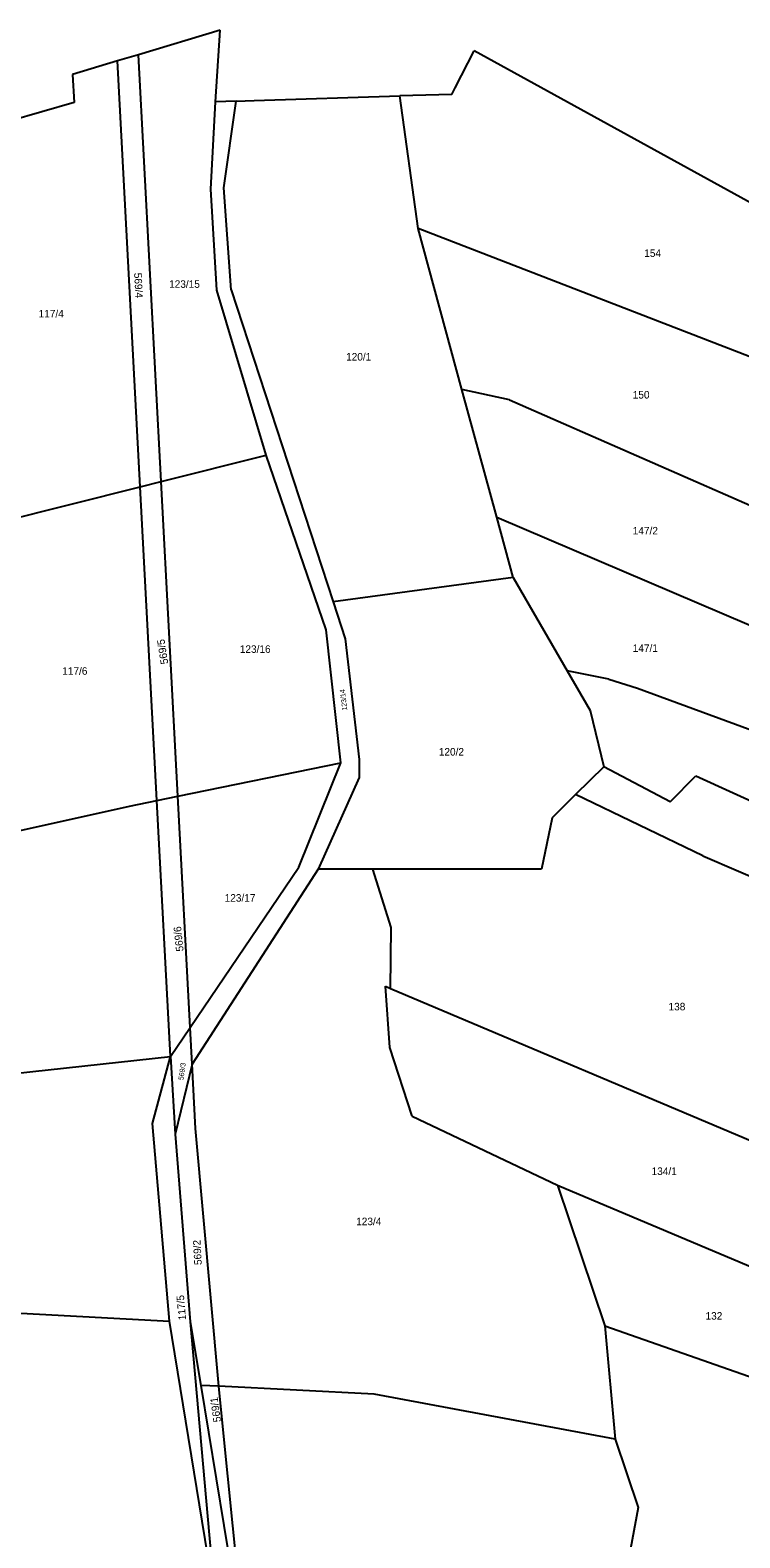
# Model space of a CAD drawing. Extents: x -664548 to -662415, y -1069720 to -1068208.
# Drawn here: x -663711.8 to -663551.7, y -1068707.2 to -1068366.8 of the extents above; entities that cross this region are included whole.
import ezdxf

# ---------------------------------------------------------------- set-up
doc = ezdxf.new("R2010")
doc.units = 0
doc.header["$LTSCALE"] = 0.68
doc.layers.add('1', color=7, linetype='Continuous', lineweight=25)
doc.layers.add('2', color=7, linetype='Continuous')

msp = doc.modelspace()

# ---------------------------------------------------------------- linework, layer by layer
at = {"layer": '1'}
for p, q in [((-663668.96, -1068366.83), (-663687.39, -1068372.38)), ((-663670.03, -1068382.99), (-663668.96, -1068366.83)), ((-663687.39, -1068372.38), (-663692.09, -1068373.79)), ((-663682.27, -1068468.73), (-663687.39, -1068372.38)), ((-663615.91, -1068379.83), (-663611.63, -1068371.51)), ((-663510.93, -1068426.96), (-663611.63, -1068371.51)), ((-663692.09, -1068373.79), (-663702.26, -1068376.85)), ((-663686.99, -1068469.92), (-663692.09, -1068373.79)), ((-663702.26, -1068376.85), (-663701.89, -1068383.2)), ((-663616.68, -1068381.33), (-663615.91, -1068379.83)), ((-663671.04, -1068402.75), (-663670.03, -1068382.99)), ((-663665.32, -1068382.84), (-663670.03, -1068382.99)), ((-663668.15, -1068402.4), (-663665.32, -1068382.84)), ((-663665.32, -1068382.84), (-663661.3, -1068382.71)), ((-663661.3, -1068382.71), (-663628.4, -1068381.69)), ((-663616.68, -1068381.33), (-663628.4, -1068381.69)), ((-663624.26, -1068411.59), (-663628.4, -1068381.69)), ((-663669.72, -1068425.56), (-663671.04, -1068402.75)), ((-663666.43, -1068425.46), (-663668.15, -1068402.4)), ((-663614.38, -1068447.93), (-663624.26, -1068411.59)), ((-663519.8, -1068452.04), (-663624.26, -1068411.59)), ((-663658.6, -1068462.76), (-663669.72, -1068425.56)), ((-663666.43, -1068425.46), (-663643.45, -1068495.92)), ((-663606.54, -1068476.78), (-663614.38, -1068447.93)), ((-663603.68, -1068450.3), (-663614.38, -1068447.93)), ((-663603.68, -1068450.3), (-663533.07, -1068481.24)), ((-663682.27, -1068468.73), (-663658.6, -1068462.76)), ((-663645, -1068502.25), (-663658.6, -1068462.76)), ((-663718.82, -1068477.94), (-663686.99, -1068469.92)), ((-663686.99, -1068469.92), (-663682.27, -1068468.73)), ((-663683.22, -1068540.77), (-663686.99, -1068469.92)), ((-663678.49, -1068539.81), (-663682.27, -1068468.73)), ((-663606.54, -1068476.78), (-663540.81, -1068504.87)), ((-663602.84, -1068490.38), (-663606.54, -1068476.78)), ((-663602.84, -1068490.38), (-663643.45, -1068495.92)), ((-663602.84, -1068490.38), (-663590.66, -1068511.46)), ((-663643.45, -1068495.92), (-663640.73, -1068504.27)), ((-663641.68, -1068532.29), (-663645, -1068502.25)), ((-663640.73, -1068504.27), (-663637.61, -1068531.5)), ((-663581.2, -1068513.39), (-663590.66, -1068511.46)), ((-663590.66, -1068511.46), (-663585.48, -1068520.42)), ((-663581.2, -1068513.39), (-663574.76, -1068515.36)), ((-663574.76, -1068515.36), (-663547.52, -1068525.38)), ((-663585.48, -1068520.42), (-663582.39, -1068533.13)), ((-663678.49, -1068539.81), (-663641.68, -1068532.29)), ((-663651.18, -1068555.78), (-663641.68, -1068532.29)), ((-663637.61, -1068531.5), (-663637.61, -1068535.54)), ((-663582.39, -1068533.13), (-663588.75, -1068539.42)), ((-663567.42, -1068541.08), (-663582.39, -1068533.13)), ((-663637.61, -1068535.54), (-663646.8, -1068556.28)), ((-663567.42, -1068541.08), (-663561.6, -1068535.16)), ((-663561.6, -1068535.16), (-663516.03, -1068556.05)), ((-663683.22, -1068540.77), (-663678.49, -1068539.81)), ((-663675.72, -1068591.99), (-663678.49, -1068539.81)), ((-663588.75, -1068539.42), (-663594.02, -1068544.64)), ((-663560.05, -1068553.23), (-663588.75, -1068539.42)), ((-663724.59, -1068549.85), (-663689.38, -1068542.03)), ((-663689.38, -1068542.03), (-663683.22, -1068540.77)), ((-663680.15, -1068598.53), (-663683.22, -1068540.77)), ((-663594.02, -1068544.64), (-663596.41, -1068556.23)), ((-663560.05, -1068553.23), (-663513.99, -1068573.2)), ((-663675.72, -1068591.99), (-663651.18, -1068555.78)), ((-663646.8, -1068556.28), (-663675.28, -1068600.26)), ((-663634.47, -1068556.27), (-663646.8, -1068556.28)), ((-663596.41, -1068556.23), (-663634.47, -1068556.27)), ((-663630.33, -1068569.44), (-663634.47, -1068556.27)), ((-663630.49, -1068583.18), (-663630.33, -1068569.44)), ((-663631.66, -1068582.68), (-663630.49, -1068583.18)), ((-663630.64, -1068596.52), (-663631.66, -1068582.68)), ((-663630.49, -1068583.18), (-663514.49, -1068632.2)), ((-663680.15, -1068598.53), (-663675.72, -1068591.99)), ((-663675.28, -1068600.26), (-663675.72, -1068591.99)), ((-663625.62, -1068612.05), (-663630.64, -1068596.52)), ((-663765.69, -1068607.89), (-663680.15, -1068598.53)), ((-663684.19, -1068613.69), (-663680.15, -1068598.53)), ((-663680.15, -1068598.53), (-663679.08, -1068616.06)), ((-663680.4, -1068658.35), (-663684.19, -1068613.69)), ((-663669.22, -1068673.02), (-663674.51, -1068614.82)), ((-663625.62, -1068612.05), (-663592.82, -1068627.59)), ((-663679.08, -1068616.06), (-663675.71, -1068658.49)), ((-663592.82, -1068627.59), (-663530.79, -1068653.83)), ((-663592.82, -1068627.59), (-663582.1, -1068659.34)), ((-663770.36, -1068653.5), (-663680.4, -1068658.35)), ((-663670.04, -1068721.72), (-663680.4, -1068658.35)), ((-663675.71, -1068658.49), (-663673.35, -1068672.81)), ((-663675.71, -1068658.49), (-663670.04, -1068721.72)), ((-663582.1, -1068659.34), (-663579.83, -1068684.94)), ((-663582.1, -1068659.34), (-663534.68, -1068676.07)), ((-663669.22, -1068673.02), (-663673.35, -1068672.81)), ((-663673.35, -1068672.81), (-663662.72, -1068737.3)), ((-663668.3, -1068682.85), (-663669.22, -1068673.02)), ((-663634.18, -1068674.82), (-663669.22, -1068673.02)), ((-663579.83, -1068684.94), (-663634.18, -1068674.82)), ((-663662.72, -1068737.3), (-663668.3, -1068682.85)), ((-663579.83, -1068684.94), (-663574.64, -1068700.41)), ((-663574.64, -1068700.41), (-663584.45, -1068754.3))]:
    msp.add_line(p, q, dxfattribs=at)
for points in [[(-663701.89, -1068383.2), (-663738.45, -1068393.73), (-663804.55, -1068418.24)], [(-663674.51, -1068614.82), (-663675.28, -1068600.26), (-663679.08, -1068616.06)]]:
    msp.add_lwpolyline(points, dxfattribs=at)

# ---------------------------------------------------------------- texts
at = {"layer": '2'}
for s, p in [('154', (-663573.24, -1068418.025)), ('123/15', (-663680.48, -1068425.005)), ('117/4', (-663709.92, -1068431.695)), ('120/1', (-663640.53, -1068441.425)), ('150', (-663575.84, -1068450.005)), ('147/2', (-663575.84, -1068480.695)), ('123/16', (-663664.52, -1068507.425)), ('147/1', (-663575.84, -1068507.215)), ('117/6', (-663704.59, -1068512.375)), ('120/2', (-663619.61, -1068530.615)), ('123/17', (-663667.94, -1068563.604)), ('138', (-663567.76, -1068588.145)), ('134/1', (-663571.58, -1068625.314)), ('123/4', (-663638.26, -1068636.645)), ('132', (-663559.41, -1068657.975))]:
    msp.add_text(s, height=1.7, dxfattribs=at).set_placement(p)
for s, height, rotation, p in [('569/4', 1.7, 273, (-663688.374, -1068421.652)), ('569/5', 1.7, 99, (-663680.65, -1068509.853)), ('123/14', 1.14, 97, (-663640.257, -1068520.375)), ('569/6', 1.7, 96, (-663677.197, -1068574.765)), ('569/3', 1.14, 82, (-663677.267, -1068603.949)), ('569/2', 1.7, 93, (-663673.095, -1068645.607)), ('117/5', 1.7, 95, (-663676.636, -1068658.032)), ('569/1', 1.7, 98, (-663668.759, -1068681))]:
    msp.add_text(s, height=height, rotation=rotation, dxfattribs=at).set_placement(p)

doc.saveas('drawing.dxf')
